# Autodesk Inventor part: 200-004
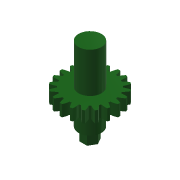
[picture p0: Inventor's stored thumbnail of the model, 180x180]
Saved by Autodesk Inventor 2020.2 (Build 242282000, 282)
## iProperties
Manager: www.cadconsulting.pl
Company: Fabian Stasiak CAD Consulting
CustomPartVersion: 1
Created: 2014-01
Part Number: 200-004
Material: Steel
Document SubType Name: Modeling
Designer: F.Stasiak
Categories: <?xml version="1.0" encoding="UTF-16"?> <MemberInstance><Categories><FamilyTemplate><FamilyTemplateParameter ValueType="xs:double" Id="1" ObjectReferenceKey="da
Density: 1 g/cm^3
Appearance: Zieleń leśna
Author: F.Stasiak
Subject: Zbiór ćwiczeń. Autodesk Inventor 2020. Kurs podstawowy
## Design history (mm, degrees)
sketch "Sketch1"
  geometry: C1 r 25.433 at (0, 0)
  constraints: 1 centre point
  dimensions: "d0" = 50.86512 diameter of C1 (= da_da)
extrude "Extrusion1" new body sketch "Sketch1" distance "d1" = 10 (= da_b); taper "d2" = 0 deg
workplane "Work Plane2"
sketch "Sketch2"
  geometry: C1 r 25.433 at (0, 0) reference; C2 r 22.535 at (0, 0)
  constraints: 1 centre point, 1 coincident
  dimensions: "d3" = 45.07042 diameter of C2 (= da_dw)
feature "Średnica podziałowa" sketch "Sketch2" dims "d4" = 10, "d5" = 0
workplane "Work Plane8"
workplane "Work Plane9"
feature "Przekładnia walcowa" dims "da_b" = 10, "da_d" = 45, "da_aw" = 80, "da_da" = 50.86512, "da_df" = 40.74159, "da_dw" = 45.07042, angle "da_beta" = 0 deg, "da_lefttooth" = 0, "da_righttooth" = 0
sketch "Szkic3"
  geometry: C1 r 10 at (0, 0); A1 r 25.433 centre (0, 0) between (-6.903, 24.478) and (-8.803, 23.861) reference
  constraints: 1 centre point, 1 coincident
  dimensions: "d49" = 20 diameter of C1
extrude "Wyciągnięcie proste2" join sketch "Szkic3" distance "d50" = 35; taper "d51" = 0 deg
sketch "Szkic4"
  geometry: C1 r 10 at (0, 0); A1 r 20.371 centre (0, 0) between (9.954, 17.773) and (8.528, 18.5) reference
  constraints: 1 centre point, 1 coincident
  dimensions: "d52" = 20 diameter of C1
extrude "Wyciągnięcie proste3" join sketch "Szkic4" distance "d53" = 20; taper "d54" = 0 deg
sketch "Szkic5"
  geometry: L1 (-3.464, -6)-(-6.928, 0); L2 (-6.928, 0)-(-3.464, 6); L3 (-3.464, 6)-(3.464, 6); L4 (3.464, 6)-(6.928, 0); L5 (6.928, 0)-(3.464, -6); L6 (3.464, -6)-(-3.464, -6); C1 r 10 at (0, 0) reference; 1 further point
  constraints: 12 end point, 1 coincident, 13 other
  dimensions: "d55" = 12 distance between parallel lines of L6 L3
extrude "Wyciągnięcie proste4" join sketch "Szkic5" distance "d56" = 10; taper "d57" = 0 deg
body "Solid1"
body "Srf1"
other parameters: "d17" = 0, "d34" = 9 deg (computed from da_z), "d39" = 0, "d41" = 0, "d47" = 0, "d48" = 0
